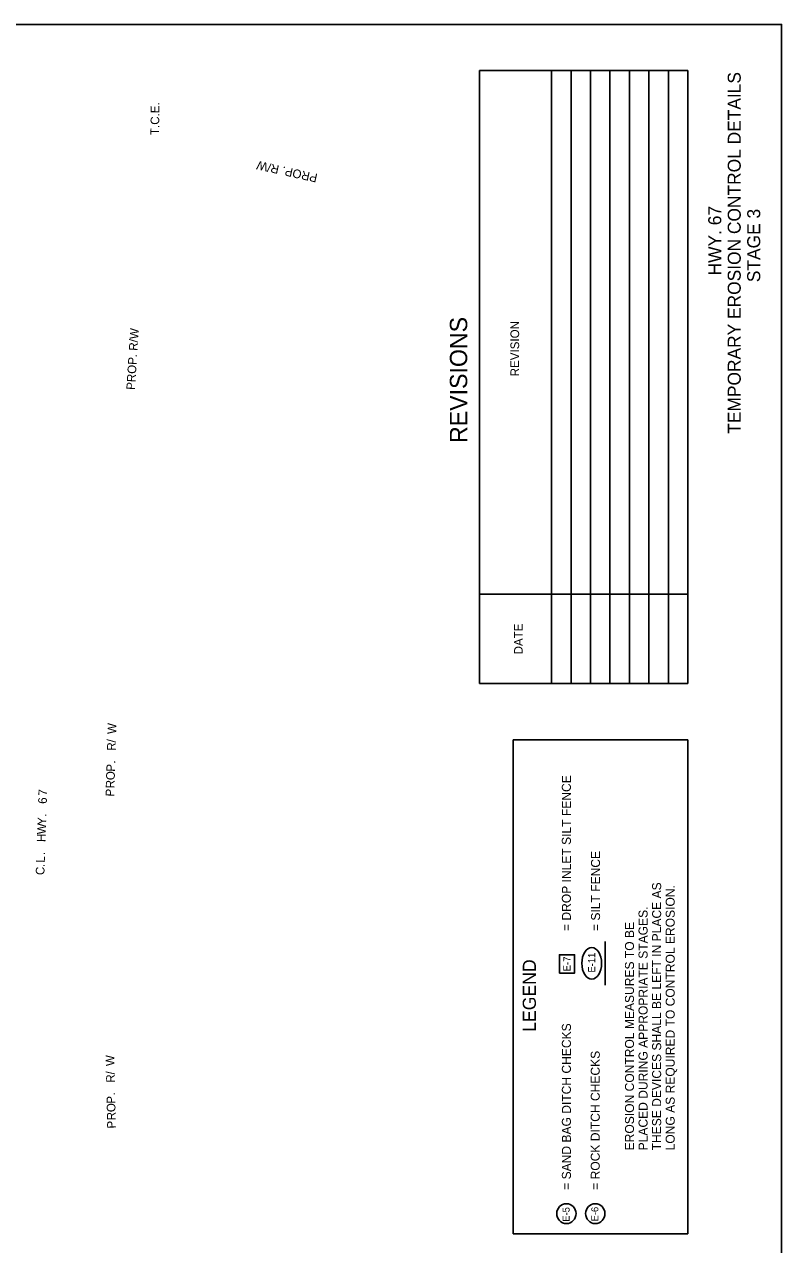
# Model space of a CAD drawing. Extents: x 991974 to 993016, y 1842702 to 1844298.
# Drawn here: x 992491 to 993016, y 1843452 to 1844298 of the extents above; entities that cross this region are included whole.
import ezdxf

# ---------------------------------------------------------------- set-up
doc = ezdxf.new("R2010")
doc.units = 0
for name, color, linetype in [('1', 7, 'Continuous'), ('60', 7, 'Continuous'), ('Default', 7, 'Continuous'), ('G-Border-Sheet', 7, 'Continuous'), ('Level 1', 7, 'Continuous'), ('Level 44', 7, 'Continuous'), ('R_Draft', 7, 'Continuous')]:
    doc.layers.add(name, color=color, linetype=linetype)

msp = doc.modelspace()

# ---------------------------------------------------------------- linework, layer by layer
at = {"layer": '1'}
msp.add_lwpolyline([(992862.32, 1843640.1), (992862.32, 1843652.85), (992872.83, 1843652.85), (992872.83, 1843640.1)], close=True, dxfattribs=at)
at = {"layer": 'Default'}
msp.add_lwpolyline([(993016.34, 1842702.47), (991974.02, 1842702.47), (991974.02, 1843999.48), (992023.57, 1843999.48), (992023.57, 1844170.33), (992171.07, 1844170.33), (992171.07, 1844297.83), (993016.34, 1844297.83)], close=True, dxfattribs=at)
msp.add_lwpolyline([(993016.34, 1842702.47), (991974.02, 1842702.47), (991974.02, 1843999.48), (992023.57, 1843999.48), (992023.57, 1844170.33), (992171.07, 1844170.33), (992171.07, 1844297.83), (993016.34, 1844297.83)], close=True, dxfattribs=at)
msp.add_lwpolyline([(993016.34, 1842702.47), (991974.02, 1842702.47), (991974.02, 1843999.48), (992023.57, 1843999.48), (992023.57, 1844170.33), (992171.07, 1844170.33), (992171.07, 1844297.83), (993016.34, 1844297.83)], close=True, dxfattribs=at)
at = {"layer": 'G-Border-Sheet'}
for p, q in [((992951.38, 1843801.93), (992830.33, 1843801.93)), ((992830.33, 1843459.27), (992830.33, 1843801.93)), ((992951.38, 1843459.27), (992951.38, 1843801.93)), ((992951.38, 1843459.27), (992830.33, 1843459.27))]:
    msp.add_line(p, q, dxfattribs=at)
at = {"layer": 'Level 1'}
for centre, major_axis, ratio in [((992884.7, 1843646.9), (0, 10.96), 0.622952), ((992867.16, 1843473.37), (0, -6.88), 0.97521), ((992887.16, 1843473.37), (0, -6.88), 0.97521)]:
    msp.add_ellipse(centre, major_axis=major_axis, ratio=ratio, dxfattribs=at)
at = {"layer": 'Level 44'}
msp.add_lwpolyline([(992894.03, 1843631.84), (992894.02, 1843661.96)], dxfattribs=at)
at = {"layer": 'R_Draft'}
for p, q in [((992806.88, 1843840.99), (992806.88, 1844265.99)), ((992806.88, 1844265.99), (992951.38, 1844265.99)), ((992856.88, 1843840.99), (992856.88, 1844265.99)), ((992870.38, 1843840.99), (992870.38, 1844265.99)), ((992883.88, 1843840.99), (992883.88, 1844265.99)), ((992897.38, 1843840.99), (992897.38, 1844265.99)), ((992897.38, 1843840.99), (992897.38, 1844265.99)), ((992910.88, 1843840.99), (992910.88, 1844265.99)), ((992924.38, 1843840.99), (992924.38, 1844265.99)), ((992937.88, 1843840.99), (992937.88, 1844265.99)), ((992951.38, 1843840.99), (992951.38, 1844265.99)), ((992806.88, 1843902.8), (992951.38, 1843902.8)), ((992806.88, 1843840.99), (992951.38, 1843840.99))]:
    msp.add_line(p, q, dxfattribs=at)

# ---------------------------------------------------------------- texts
at = {"layer": '1'}
msp.add_text('E-7 ', height=4.999, rotation=89.61212, dxfattribs=at).set_placement((992870.01, 1843641.26))
at = {"layer": '60'}
for s, p in [('TEMPORARY EROSION CONTROL DETAILS', (992988.01, 1844014.05)), ('HWY. 67 ', (992974.51, 1844123.82)), (' STAGE 3', (993001.51, 1844115.78))]:
    msp.add_text(s, height=9, rotation=90, dxfattribs=at).set_placement(p)
at = {"layer": 'Level 1'}
for s, height, p in [('= DROP INLET SILT FENCE', 6.25, (992870.26, 1843669.33)), ('= SILT FENCE', 6.25, (992890.48, 1843669.33)), ('THESE DEVICES SHALL BE LEFT IN PLACE AS ', 6.25, (992932.84, 1843517.24)), ('LONG AS REQUIRED TO CONTROL EROSION.', 6.25, (992942.25, 1843517.24)), ('PLACED DURING APPROPRIATE STAGES. ', 6.25, (992923.43, 1843517.24)), ('EROSION CONTROL MEASURES TO BE', 6.25, (992914.02, 1843517.24)), ('E-11 ', 4.876, (992887.1, 1843640.5)), ('= SAND BAG DITCH CHECKS', 6.25, (992870.28, 1843489.9)), ('= ROCK DITCH CHECKS', 6.25, (992890.28, 1843489.9)), ('E-5 ', 4.876, (992869.38, 1843467.73)), ('E-6 ', 4.876, (992889.29, 1843467.95))]:
    msp.add_text(s, height=height, rotation=90.00001, dxfattribs=at).set_placement(p)
at = {"layer": 'Level 44'}
msp.add_text('LEGEND', height=9.143, rotation=90.00001, dxfattribs=at).set_placement((992846.03, 1843599.41))
at = {"layer": 'R_Draft'}
for s, height, rotation, p in [('T.C.E.', 6, 89.40901, (992584.79, 1844221.09)), ('PROP. R/W', 6, 167.44815, (992695, 1844194.05)), ('REVISIONS', 12, 90, (992798.38, 1844007.65)), ('REVISION', 6, 90, (992834.38, 1844053.86)), ('PROP. R/W', 6, 86.36556, (992568.04, 1844044.29)), ('DATE', 6, 90, (992836.88, 1843861.06)), ('W', 6, 88.2004, (992554.98, 1843805.77)), ('/', 6, 88.2004, (992554.8, 1843799.91)), ('R', 6, 88.2004, (992554.62, 1843794.24)), ('P', 6, 88.2004, (992554.16, 1843779.65)), ('.', 6, 88.2004, (992554.34, 1843785.32)), ('O', 6, 88.2004, (992553.98, 1843773.8)), ('7', 6, 88.03611, (992507.11, 1843763.04)), ('P', 6, 88.2004, (992553.62, 1843762.47)), ('R', 6, 88.2004, (992553.8, 1843768.13)), ('6', 6, 88.03611, (992506.91, 1843757.38)), ('W', 6, 88.03611, (992506.19, 1843736.27)), ('Y', 6, 88.03611, (992506.41, 1843742.69)), ('.', 6, 88.03611, (992506.61, 1843748.45)), ('H', 6, 88.03611, (992506, 1843730.89)), ('L', 6, 88.03611, (992505.51, 1843716.58)), ('.', 6, 88.03611, (992505.7, 1843721.96)), ('C', 6, 88.03611, (992505.22, 1843707.99)), ('.', 6, 88.03611, (992505.41, 1843713.65)), ('W', 6, 91.21594, (992553.9, 1843575.77)), ('/', 6, 91.21594, (992554.03, 1843569.92)), ('R', 6, 91.21594, (992554.15, 1843564.25)), ('.', 6, 91.21594, (992554.34, 1843555.32)), ('P', 6, 91.21594, (992554.46, 1843549.65)), ('O', 6, 91.21594, (992554.58, 1843543.8)), ('R', 6, 91.21594, (992554.7, 1843538.13)), ('P', 6, 91.21594, (992554.82, 1843532.46))]:
    msp.add_text(s, height=height, rotation=rotation, dxfattribs=at).set_placement(p)

doc.saveas('drawing.dxf')
